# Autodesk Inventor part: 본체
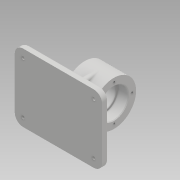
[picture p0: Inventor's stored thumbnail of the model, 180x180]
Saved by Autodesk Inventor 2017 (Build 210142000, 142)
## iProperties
Part Number: 본체
Material: 일반
Document SubType Name: Modeling
Designer: 603-17
Density: 1 g/cm^3
Appearance: 기본값
Author: 603-17
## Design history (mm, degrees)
sketch "스케치1"
  geometry: L1 (63, 49)-(-63, 49); L2 (-63, 49)-(-63, -49); L3 (-63, -49)-(63, -49); L4 (63, -49)-(63, 49); L5 (63, 49)-(-63, -49); L6 (-63, 49)-(63, -49); 1 further point
  constraints: 12 end point, 2 midpoint, 2 parallel, 1 horizontal, 1 perpendicular
  dimensions: "d0" = 126 distance of L2.end L3.end; "d1" = 98 distance of L1.end L2.end
extrude "돌출1" new body sketch "스케치1" distance "d2" = 9; taper "d3" = 0 deg
node "작업 평면1"
sketch "스케치2"
  geometry: L1 (0, 49)-(9, 49) reference; L2 (9, 49)-(9, -49) reference; L3 (9, -49)-(0, -49) reference; L4 (0, -49)-(0, 49) reference; L5 (0, 49)-(0, -13); L6 (0, -13)-(59, -13); C1 r 32 at (59, -13); 1 further point
  constraints: 4 end point, 1 centre point, 1 coincident, 1 horizontal, 1 vertical
  dimensions: "d5" = 62 distance of L1.start L5.end; "d6" = 59 distance of L5.end L6.end; "d7" = 64 diameter of C1
extrude "돌출2" join sketch "스케치2" stored distance "d8" = 42; taper "d9" = 0 deg
sketch "스케치3"
  geometry: L1 (0, 49)-(9, 49) reference; L2 (9, 49)-(9, -49) reference; L3 (9, -49)-(0, -49) reference; L4 (0, -49)-(0, 49) reference; L5 (59, -45)-(4.5, -45); L6 (59, 19)-(4.5, 19); L7 (4.5, -45)-(4.5, 19); A1 r 32 centre (59, -13) between (59, -45) and (59, 19) reference; 1 further point
  constraints: 6 end point, 2 point on circle, 1 horizontal, 1 parallel, 1 perpendicular, 1 tangent
extrude "돌출3" join sketch "스케치3" stored distance "d10" = 8; taper "d11" = 0 deg
node "작업 평면2"
sketch "스케치4"
  geometry: L1 (126, 9)-(126, 0) reference; L2 (126, 0)-(0, 0) reference; L3 (0, 0)-(0, 9) reference; L4 (0, 9)-(59, 9) reference; L5 (59, 9)-(59, 27) reference; L6 (59, 27)-(42, 27) reference; L7 (42, 27)-(42, 91) reference; L8 (42, 91)-(84, 91) reference; L9 (84, 91)-(84, 27) reference; L10 (84, 27)-(67, 27) reference; L11 (67, 27)-(67, 9) reference; L12 (67, 9)-(126, 9) reference; L13 (46, 0)-(80, 0); L14 (80, 0)-(80, 42.607); L15 (80, 42.607)-(46, 42.607); L16 (46, 42.607)-(46, 0); 3 further points
  constraints: 8 end point, 2 coincident, 2 midpoint, 2 parallel, 1 horizontal, 1 perpendicular
  dimensions: "d13" = 34 distance of L14.end L15.end
extrude "돌출4" join sketch "스케치4" stored distance "d14" = 8; taper "d15" = 0 deg
fillet "모깎기1" dims "d16" = 12
fillet "모깎기2" dims "d17" = 3
fillet "모깎기3" dims "d18" = 3
fillet "모깎기4" dims "d19" = 3
fillet "모깎기5" dims "d20" = 3
fillet "모깎기6" dims "d21" = 3
sketch "스케치5"
  geometry: L1 (-59, -50)-(33, -50) reference; L2 (36, -53)-(36, -59) reference; L3 (36, -59)-(-62, -59) reference; L4 (-62, -59)-(-62, -53) reference; C1 r 32 at (0, 0) reference; C2 r 18 at (0, 0); A1 r 3 centre (-59, -53) between (-59, -50) and (-62, -53) reference; A2 r 3 centre (33, -53) between (36, -53) and (33, -50) reference; 1 further point
  constraints: 1 centre point, 1 coincident
  dimensions: "d22" = 36 diameter of C2
extrude "돌출5" cut sketch "스케치5" stored distance "d23" = 8; taper "d24" = 0 deg
sketch "스케치6"
  geometry: C1 r 21 at (0, 0); 1 further point
  constraints: 1 centre point
  dimensions: "d25" = 42 diameter of C1
extrude "돌출6" cut sketch "스케치6" distance "d26" = 15; taper "d27" = 0 deg
fillet "모깎기7" dims "d28" = 0.3
chamfer "모따기1" distance "d29" = 1; stored, may be unused: second distance "d30" = 2, angle "d31" = 45 deg
sketch "스케치7" dims "d32" = 52
  geometry: L1 (-59, -50)-(33, -50) reference; L2 (36, -53)-(36, -59) reference; L3 (36, -59)-(-62, -59) reference; L4 (-62, -59)-(-62, -53) reference; L5 (0, 0)-(0, 26); C1 r 22 at (0, 0) reference; C2 r 32 at (0, 0) reference; A1 r 3 centre (-59, -53) between (-59, -50) and (-62, -53) reference; A2 r 3 centre (33, -53) between (36, -53) and (33, -50) reference; 1 further point
  constraints: 2 end point, 1 coincident, 1 vertical, 1 vertical alignment, 2 other
hole "구멍1" sketch "스케치7" at (0, 26) diameter "d33" = 3.459; stored, may be unused: countersink angle "d37" = 90 deg, drill point angle "d39" = 118 deg; dims "d34" = 8, "d35" = 4, "d36" = 2, "d38" = 10
sketch "스케치8"
  geometry: L1 (60, -37)-(60, 37) reference; L2 (51, 46)-(5.472, 46) reference; L3 (-1, 46.607)-(1, 46.607) reference; L4 (-5.472, 46)-(-51, 46) reference; L5 (-60, 37)-(-60, -37) reference; L6 (-51, -46)-(51, -46) reference; L7 (7, 20)-(7, 42) reference; L8 (14, 20)-(7, 20) reference; L9 (20, 12)-(20, 14) reference; L10 (7, 6)-(14, 6) reference; L11 (7, -16)-(7, 6) reference; L12 (-1, -22)-(1, -22) reference; L13 (-7, 6)-(-7, -16) reference; L14 (-14, 6)-(-7, 6) reference; L15 (-20, 14)-(-20, 12) reference; L16 (-7, 20)-(-14, 20) reference; L17 (-7, 42)-(-7, 20) reference; C1 r 2.25 at (51, 37); C2 r 2.25 at (-51, 37); C3 r 2.25 at (-51, -37); C4 r 2.25 at (51, -37); A1 r 9 centre (51, -37) between (51, -46) and (60, -37) reference; A2 r 9 centre (51, 37) between (60, 37) and (51, 46) reference; A3 r 9 centre (-51, 37) between (-51, 46) and (-60, 37) reference; A4 r 9 centre (-51, -37) between (-60, -37) and (-51, -46) reference; A5 r 6 centre (1, 42) between (7, 42) and (5.472, 46) reference; A6 r 6 centre (14, 14) between (20, 14) and (14, 20) reference; A7 r 6 centre (14, 12) between (14, 6) and (20, 12) reference; A8 r 6 centre (1, -16) between (1, -22) and (7, -16) reference; A9 r 6 centre (-1, -16) between (-7, -16) and (-1, -22) reference; A10 r 6 centre (-14, 12) between (-20, 12) and (-14, 6) reference; A11 r 6 centre (-14, 14) between (-14, 20) and (-20, 14) reference; A12 r 6 centre (-1, 42) between (-5.472, 46) and (-7, 42) reference; 1 further point
  constraints: 4 centre point, 4 coincident, 2 other
  dimensions: "d43" = 4.5 diameter of C2; "d44" = 4.5 diameter of C1; "d45" = 4.5 diameter of C3; "d46" = 4.5 diameter of C4
extrude "돌출7" cut sketch "스케치8" stored distance "d47" = 15; taper "d48" = 0 deg
sketch "스케치9"
  geometry: L1 (60, -37)-(60, 37) reference; L2 (51, 46)-(5.472, 46) reference; L3 (-1, 46.607)-(1, 46.607) reference; L4 (-5.472, 46)-(-51, 46) reference; L5 (-60, 37)-(-60, -37) reference; L6 (-51, -46)-(51, -46) reference; L7 (7, 20)-(7, 42) reference; L8 (14, 20)-(7, 20) reference; L9 (20, 12)-(20, 14) reference; L10 (7, 6)-(14, 6) reference; L11 (7, -16)-(7, 6) reference; L12 (-1, -22)-(1, -22) reference; L13 (-7, 6)-(-7, -16) reference; L14 (-14, 6)-(-7, 6) reference; L15 (-20, 14)-(-20, 12) reference; L16 (-7, 20)-(-14, 20) reference; L17 (-7, 42)-(-7, 20) reference; C1 r 2.25 at (-51, -37) reference; C2 r 2.25 at (51, 37) reference; C3 r 2.25 at (-51, 37) reference; C4 r 2.25 at (51, -37) reference; C5 r 4 at (-51, 37); C6 r 4 at (51, 37); C7 r 4 at (51, -37); C8 r 4 at (-51, -37); A1 r 9 centre (51, -37) between (51, -46) and (60, -37) reference; A2 r 9 centre (51, 37) between (60, 37) and (51, 46) reference; A3 r 9 centre (-51, 37) between (-51, 46) and (-60, 37) reference; A4 r 9 centre (-51, -37) between (-60, -37) and (-51, -46) reference; A5 r 6 centre (1, 42) between (7, 42) and (5.472, 46) reference; A6 r 6 centre (14, 14) between (20, 14) and (14, 20) reference; A7 r 6 centre (14, 12) between (14, 6) and (20, 12) reference; A8 r 6 centre (1, -16) between (1, -22) and (7, -16) reference; A9 r 6 centre (-1, -16) between (-7, -16) and (-1, -22) reference; A10 r 6 centre (-14, 12) between (-20, 12) and (-14, 6) reference; A11 r 6 centre (-14, 14) between (-14, 20) and (-20, 14) reference; A12 r 6 centre (-1, 42) between (-5.472, 46) and (-7, 42) reference; 1 further point
  constraints: 4 centre point, 4 coincident, 2 other
  dimensions: "d49" = 8 diameter of C5; "d50" = 8 diameter of C6; "d51" = 8 diameter of C7; "d52" = 8 diameter of C8
extrude "돌출8" cut sketch "스케치9" distance "d53" = 4.4; taper "d54" = 0 deg
sketch "스케치11"
  geometry: L1 (60, -37)-(60, 37) reference; L2 (51, 46)-(5.472, 46) reference; L3 (-1, 46.607)-(1, 46.607) reference; L4 (-5.472, 46)-(-51, 46) reference; L5 (-60, 37)-(-60, -37) reference; L6 (-51, -46)-(51, -46) reference; L7 (7, 20)-(7, 42) reference; L8 (14, 20)-(7, 20) reference; L9 (20, 12)-(20, 14) reference; L10 (7, 6)-(14, 6) reference; L11 (7, -16)-(7, 6) reference; L12 (-1, -22)-(1, -22) reference; L13 (-7, 6)-(-7, -16) reference; L14 (-14, 6)-(-7, 6) reference; L15 (-20, 14)-(-20, 12) reference; L16 (-7, 20)-(-14, 20) reference; L17 (-7, 42)-(-7, 20) reference; L18 (29.03, -19.34)-(-29.03, -19.34); L19 (-29.03, -19.34)-(-29.03, -58.66); L20 (-29.03, -58.66)-(29.03, -58.66); L21 (29.03, -58.66)-(29.03, -19.34); L22 (-51, -49)-(51, -49) reference; C1 r 4 at (51, -37) reference; C2 r 4 at (-51, 37) reference; C3 r 4 at (51, 37) reference; C4 r 4 at (-51, -37) reference; A1 r 9 centre (51, -37) between (51, -46) and (60, -37) reference; A2 r 9 centre (51, 37) between (60, 37) and (51, 46) reference; A3 r 9 centre (-51, 37) between (-51, 46) and (-60, 37) reference; A4 r 9 centre (-51, -37) between (-60, -37) and (-51, -46) reference; A5 r 6 centre (1, 42) between (7, 42) and (5.472, 46) reference; A6 r 6 centre (14, 14) between (20, 14) and (14, 20) reference; A7 r 6 centre (14, 12) between (14, 6) and (20, 12) reference; A8 r 6 centre (1, -16) between (1, -22) and (7, -16) reference; A9 r 6 centre (-1, -16) between (-7, -16) and (-1, -22) reference; A10 r 6 centre (-14, 12) between (-20, 12) and (-14, 6) reference; A11 r 6 centre (-14, 14) between (-14, 20) and (-20, 14) reference; A12 r 6 centre (-1, 42) between (-5.472, 46) and (-7, 42) reference; 5 further points
  constraints: 2 midpoint, 4 other
  dimensions: "d55" = 3 distance between parallel lines of L22 L6 (derived)
feature "엠보싱1" sketch "스케치11" dims "d0" = 126, "d1" = 98, "d58" = 0.5, "d59" = 0
node "솔리드1"
mirror "미러1"
pattern_circular "원형 패턴1" dims angle "d41" = 360 deg
mirror "미러2"
node "절단 모서리 투영1"
node "절단 모서리 투영2"
node "절단 모서리 투영3"
node "절단 모서리 투영4"
node "절단 모서리 투영5"
node "절단 모서리 투영6"
node "절단 모서리 투영7"
node "절단 모서리 투영9"
other parameters: "d4" = 0, "d12" = -62
